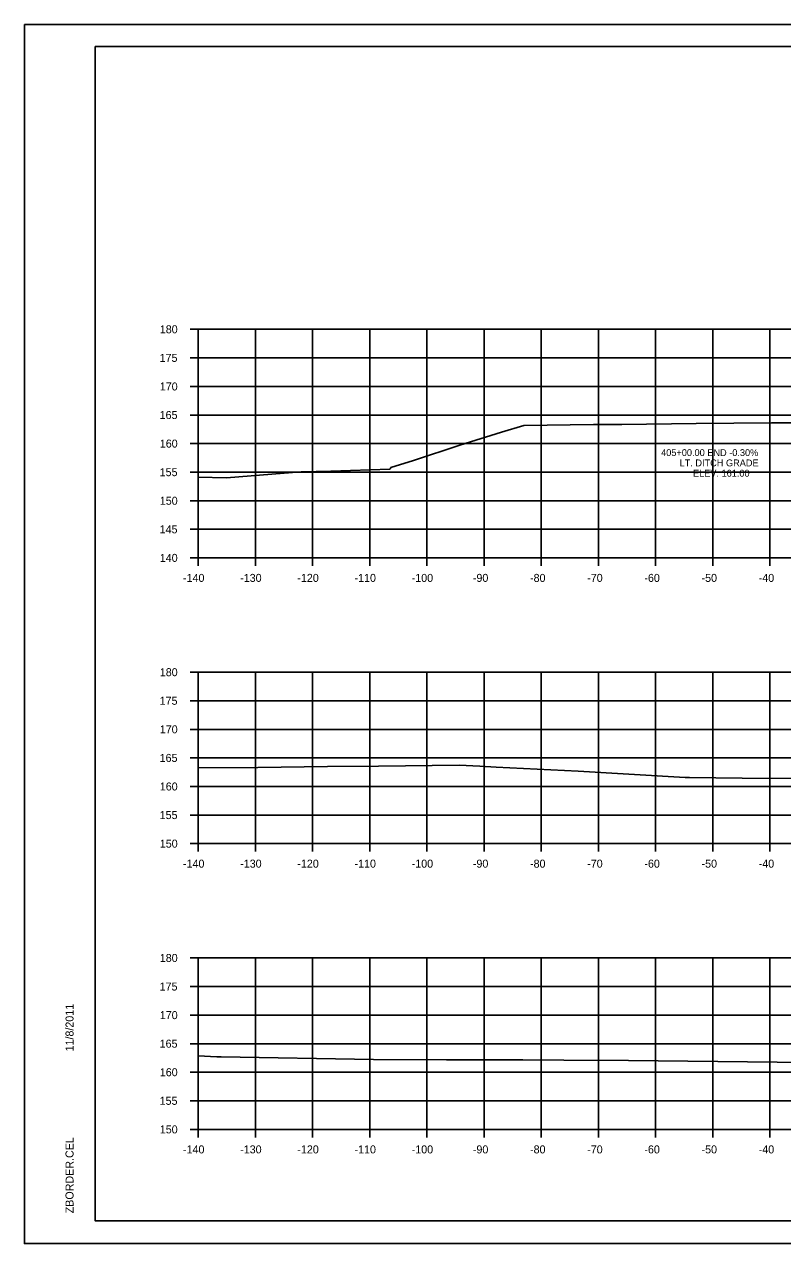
# Model space of a CAD drawing. Extents: x 1368503 to 1373085, y 379840 to 381833.
# Drawn here: x 1372751.7 to 1372884.3, y 380388.3 to 380601.6 of the extents above; entities that cross this region are included whole.
import ezdxf

# ---------------------------------------------------------------- set-up
doc = ezdxf.new("R2010")
doc.units = 0
for name, color, linetype in [('S_BRIDGE', 7, 'Continuous'), ('S_EDGE_PAVEMENT', 7, 'Continuous'), ('S_GRAVEL_ROAD', 7, 'Continuous'), ('S_MISC_BOUNDARY', 7, 'Continuous'), ('S_PHOTO_CENTERS', 7, 'Continuous'), ('S_PHOTO_NOTES', 7, 'Continuous'), ('S_TRAILS', 7, 'Continuous')]:
    doc.layers.add(name, color=color, linetype=linetype)

msp = doc.modelspace()

# ---------------------------------------------------------------- linework, layer by layer
at = {"layer": 'S_BRIDGE'}
for p, q in [((1372764.08, 380597.75), (1373080.26, 380597.75)), ((1372764.08, 380392.29), (1372764.08, 380597.75)), ((1372764.08, 380392.29), (1372764.08, 380392.29)), ((1373080.26, 380392.29), (1372764.08, 380392.29))]:
    msp.add_line(p, q, dxfattribs=at)
at = {"layer": 'S_EDGE_PAVEMENT'}
for p, q in [((1372780.68, 380548.29), (1372782.08, 380548.29)), ((1372782.08, 380508.29), (1372782.08, 380548.29)), ((1372780.68, 380543.29), (1372782.08, 380543.29)), ((1372780.68, 380538.29), (1372782.08, 380538.29)), ((1372780.68, 380533.29), (1372782.08, 380533.29)), ((1372780.68, 380528.29), (1372782.08, 380528.29)), ((1372780.68, 380523.29), (1372782.08, 380523.29)), ((1372780.68, 380518.29), (1372782.08, 380518.29)), ((1372780.68, 380513.29), (1372782.08, 380513.29)), ((1372780.68, 380508.29), (1372782.08, 380508.29)), ((1372782.08, 380508.29), (1373062.08, 380508.29)), ((1372782.08, 380506.89), (1372782.08, 380508.29)), ((1372792.08, 380506.89), (1372792.08, 380508.29)), ((1372802.08, 380506.89), (1372802.08, 380508.29)), ((1372812.08, 380506.89), (1372812.08, 380508.29)), ((1372822.08, 380506.89), (1372822.08, 380508.29)), ((1372832.08, 380506.89), (1372832.08, 380508.29)), ((1372842.08, 380506.89), (1372842.08, 380508.29)), ((1372852.08, 380506.89), (1372852.08, 380508.29)), ((1372862.08, 380506.89), (1372862.08, 380508.29)), ((1372872.08, 380506.89), (1372872.08, 380508.29)), ((1372882.08, 380506.89), (1372882.08, 380508.29)), ((1372780.68, 380488.29), (1372782.08, 380488.29)), ((1372782.08, 380458.29), (1372782.08, 380488.29)), ((1372780.68, 380483.29), (1372782.08, 380483.29)), ((1372780.68, 380478.29), (1372782.08, 380478.29)), ((1372780.68, 380473.29), (1372782.08, 380473.29)), ((1372780.68, 380468.29), (1372782.08, 380468.29)), ((1372780.68, 380463.29), (1372782.08, 380463.29)), ((1372780.68, 380458.29), (1372782.08, 380458.29)), ((1372782.08, 380458.29), (1373062.08, 380458.29)), ((1372782.08, 380456.89), (1372782.08, 380458.29)), ((1372792.08, 380456.89), (1372792.08, 380458.29)), ((1372802.08, 380456.89), (1372802.08, 380458.29)), ((1372812.08, 380456.89), (1372812.08, 380458.29)), ((1372822.08, 380456.89), (1372822.08, 380458.29)), ((1372832.08, 380456.89), (1372832.08, 380458.29)), ((1372842.08, 380456.89), (1372842.08, 380458.29)), ((1372852.08, 380456.89), (1372852.08, 380458.29)), ((1372862.08, 380456.89), (1372862.08, 380458.29)), ((1372872.08, 380456.89), (1372872.08, 380458.29)), ((1372882.08, 380456.89), (1372882.08, 380458.29)), ((1372780.68, 380438.29), (1372782.08, 380438.29)), ((1372782.08, 380408.29), (1372782.08, 380438.29)), ((1372780.68, 380433.29), (1372782.08, 380433.29)), ((1372780.68, 380428.29), (1372782.08, 380428.29)), ((1372780.68, 380423.29), (1372782.08, 380423.29)), ((1372780.68, 380418.29), (1372782.08, 380418.29)), ((1372780.68, 380413.29), (1372782.08, 380413.29)), ((1372780.68, 380408.29), (1372782.08, 380408.29)), ((1372782.08, 380408.29), (1373062.08, 380408.29)), ((1372782.08, 380406.89), (1372782.08, 380408.29)), ((1372792.08, 380406.89), (1372792.08, 380408.29)), ((1372802.08, 380406.89), (1372802.08, 380408.29)), ((1372812.08, 380406.89), (1372812.08, 380408.29)), ((1372822.08, 380406.89), (1372822.08, 380408.29)), ((1372832.08, 380406.89), (1372832.08, 380408.29)), ((1372842.08, 380406.89), (1372842.08, 380408.29)), ((1372852.08, 380406.89), (1372852.08, 380408.29)), ((1372862.08, 380406.89), (1372862.08, 380408.29)), ((1372872.08, 380406.89), (1372872.08, 380408.29)), ((1372882.08, 380406.89), (1372882.08, 380408.29))]:
    msp.add_line(p, q, dxfattribs=at)
at = {"layer": 'S_MISC_BOUNDARY'}
for points in [[(1372782.08, 380522.44), (1372787.01, 380522.28), (1372797.1, 380523.12), (1372800.11, 380523.37), (1372805.26, 380523.49), (1372815.57, 380523.82), (1372815.75, 380524.04), (1372815.78, 380524.11), (1372819.73, 380525.31), (1372827.82, 380528.02), (1372835.11, 380530.28), (1372839.04, 380531.45), (1372851.23, 380531.61), (1372856.16, 380531.65), (1372869.17, 380531.8), (1372882.35, 380531.9), (1372887.83, 380531.95)], [(1372782.08, 380471.57), (1372792.48, 380471.64), (1372804.68, 380471.78), (1372813.59, 380471.85), (1372827.71, 380472.02), (1372831.34, 380471.86), (1372834.2, 380471.69), (1372848.52, 380470.96), (1372867.24, 380469.88), (1372868.03, 380469.87), (1372877.23, 380469.76), (1372893.46, 380469.68)], [(1372782.08, 380421.19), (1372785.31, 380420.98), (1372785.7, 380420.96), (1372786.1, 380420.96), (1372812.71, 380420.53), (1372825.51, 380420.47), (1372838.84, 380420.44), (1372846.03, 380420.42), (1372857.32, 380420.34), (1372883.33, 380420.08), (1372893.58, 380419.97)]]:
    msp.add_lwpolyline(points, dxfattribs=at)
at = {"layer": 'S_PHOTO_CENTERS'}
for p, q in [((1372782.08, 380548.29), (1373062.08, 380548.29)), ((1372782.08, 380508.29), (1372782.08, 380548.29)), ((1372792.08, 380508.29), (1372792.08, 380548.29)), ((1372802.08, 380508.29), (1372802.08, 380548.29)), ((1372812.08, 380508.29), (1372812.08, 380548.29)), ((1372822.08, 380508.29), (1372822.08, 380548.29)), ((1372832.08, 380508.29), (1372832.08, 380548.29)), ((1372842.08, 380508.29), (1372842.08, 380548.29)), ((1372852.08, 380508.29), (1372852.08, 380548.29)), ((1372862.08, 380508.29), (1372862.08, 380548.29)), ((1372872.08, 380508.29), (1372872.08, 380548.29)), ((1372882.08, 380508.29), (1372882.08, 380548.29)), ((1372782.08, 380543.29), (1373062.08, 380543.29)), ((1372782.08, 380538.29), (1373062.08, 380538.29)), ((1372782.08, 380533.29), (1373062.08, 380533.29)), ((1372782.08, 380528.29), (1373062.08, 380528.29)), ((1372782.08, 380523.29), (1373062.08, 380523.29)), ((1372782.08, 380518.29), (1373062.08, 380518.29)), ((1372782.08, 380513.29), (1373062.08, 380513.29)), ((1372782.08, 380508.29), (1373062.08, 380508.29)), ((1372782.08, 380488.29), (1373062.08, 380488.29)), ((1372782.08, 380458.29), (1372782.08, 380488.29)), ((1372792.08, 380458.29), (1372792.08, 380488.29)), ((1372802.08, 380458.29), (1372802.08, 380488.29)), ((1372812.08, 380458.29), (1372812.08, 380488.29)), ((1372822.08, 380458.29), (1372822.08, 380488.29)), ((1372832.08, 380458.29), (1372832.08, 380488.29)), ((1372842.08, 380458.29), (1372842.08, 380488.29)), ((1372852.08, 380458.29), (1372852.08, 380488.29)), ((1372862.08, 380458.29), (1372862.08, 380488.29)), ((1372872.08, 380458.29), (1372872.08, 380488.29)), ((1372882.08, 380458.29), (1372882.08, 380488.29)), ((1372782.08, 380483.29), (1373062.08, 380483.29)), ((1372782.08, 380478.29), (1373062.08, 380478.29)), ((1372782.08, 380473.29), (1373062.08, 380473.29)), ((1372782.08, 380468.29), (1373062.08, 380468.29)), ((1372782.08, 380463.29), (1373062.08, 380463.29)), ((1372782.08, 380458.29), (1373062.08, 380458.29)), ((1372782.08, 380438.29), (1373062.08, 380438.29)), ((1372782.08, 380408.29), (1372782.08, 380438.29)), ((1372792.08, 380408.29), (1372792.08, 380438.29)), ((1372802.08, 380408.29), (1372802.08, 380438.29)), ((1372812.08, 380408.29), (1372812.08, 380438.29)), ((1372822.08, 380408.29), (1372822.08, 380438.29)), ((1372832.08, 380408.29), (1372832.08, 380438.29)), ((1372842.08, 380408.29), (1372842.08, 380438.29)), ((1372852.08, 380408.29), (1372852.08, 380438.29)), ((1372862.08, 380408.29), (1372862.08, 380438.29)), ((1372872.08, 380408.29), (1372872.08, 380438.29)), ((1372882.08, 380408.29), (1372882.08, 380438.29)), ((1372782.08, 380433.29), (1373062.08, 380433.29)), ((1372782.08, 380428.29), (1373062.08, 380428.29)), ((1372782.08, 380423.29), (1373062.08, 380423.29)), ((1372782.08, 380418.29), (1373062.08, 380418.29)), ((1372782.08, 380413.29), (1373062.08, 380413.29)), ((1372782.08, 380408.29), (1373062.08, 380408.29))]:
    msp.add_line(p, q, dxfattribs=at)
at = {"layer": 'S_PHOTO_NOTES'}
for p, q in [((1372751.68, 380601.64), (1373085.01, 380601.64)), ((1372751.68, 380388.31), (1373085.01, 380388.31))]:
    msp.add_line(p, q, dxfattribs=at)
for points in [[(1372751.67, 380601.64), (1373085.01, 380601.64), (1373085.01, 380388.3), (1372751.67, 380388.3)], [(1372998, 380597.75), (1372998, 380587.87), (1373033.73, 380587.87), (1373033.73, 380584.95), (1373056.93, 380584.95), (1373056.93, 380560.61), (1373080.26, 380560.61), (1373080.26, 380392.29), (1372764.08, 380392.29), (1372764.08, 380597.75)]]:
    msp.add_lwpolyline(points, close=True, dxfattribs=at)

# ---------------------------------------------------------------- texts
at = {"layer": 'S_BRIDGE'}
for s, p in [('11/8/2011', (1372760.27, 380421.93)), ('ZBORDER.CEL', (1372760.27, 380393.61))]:
    msp.add_text(s, height=1.4, rotation=90, dxfattribs=at).set_placement(p)
at = {"layer": 'S_GRAVEL_ROAD'}
for s, p in [('405+00.00 END -0.30%', (1372863.05, 380526.11)), ('LT. DITCH GRADE', (1372866.28, 380524.31)), ('ELEV. 161.00', (1372868.62, 380522.51))]:
    msp.add_text(s, height=1.2, dxfattribs=at).set_placement(p)
at = {"layer": 'S_TRAILS'}
for s, p in [('180', (1372775.36, 380547.59)), ('175', (1372775.33, 380542.59)), ('170', (1372775.36, 380537.59)), ('165', (1372775.33, 380532.59)), ('160', (1372775.36, 380527.59)), ('155', (1372775.33, 380522.59)), ('150', (1372775.36, 380517.59)), ('145', (1372775.33, 380512.59)), ('140', (1372775.36, 380507.59)), ('-140', (1372779.42, 380504.09)), ('-130', (1372789.42, 380504.09)), ('-120', (1372799.42, 380504.09)), ('-110', (1372809.42, 380504.09)), ('-100', (1372819.42, 380504.09)), ('-90', (1372830.12, 380504.09)), ('-80', (1372840.12, 380504.09)), ('-70', (1372850.12, 380504.09)), ('-60', (1372860.12, 380504.09)), ('-50', (1372870.12, 380504.09)), ('-40', (1372880.12, 380504.09)), ('180', (1372775.36, 380487.59)), ('175', (1372775.33, 380482.59)), ('170', (1372775.36, 380477.59)), ('165', (1372775.33, 380472.59)), ('160', (1372775.36, 380467.59)), ('155', (1372775.33, 380462.59)), ('150', (1372775.36, 380457.59)), ('-140', (1372779.42, 380454.09)), ('-130', (1372789.42, 380454.09)), ('-120', (1372799.42, 380454.09)), ('-110', (1372809.42, 380454.09)), ('-100', (1372819.42, 380454.09)), ('-90', (1372830.12, 380454.09)), ('-80', (1372840.12, 380454.09)), ('-70', (1372850.12, 380454.09)), ('-60', (1372860.12, 380454.09)), ('-50', (1372870.12, 380454.09)), ('-40', (1372880.12, 380454.09)), ('180', (1372775.36, 380437.59)), ('175', (1372775.33, 380432.59)), ('170', (1372775.36, 380427.59)), ('165', (1372775.33, 380422.59)), ('160', (1372775.36, 380417.59)), ('155', (1372775.33, 380412.59)), ('150', (1372775.36, 380407.59)), ('-140', (1372779.42, 380404.09)), ('-130', (1372789.42, 380404.09)), ('-120', (1372799.42, 380404.09)), ('-110', (1372809.42, 380404.09)), ('-100', (1372819.42, 380404.09)), ('-90', (1372830.12, 380404.09)), ('-80', (1372840.12, 380404.09)), ('-70', (1372850.12, 380404.09)), ('-60', (1372860.12, 380404.09)), ('-50', (1372870.12, 380404.09)), ('-40', (1372880.12, 380404.09))]:
    msp.add_text(s, height=1.4, dxfattribs=at).set_placement(p)

doc.saveas('drawing.dxf')
